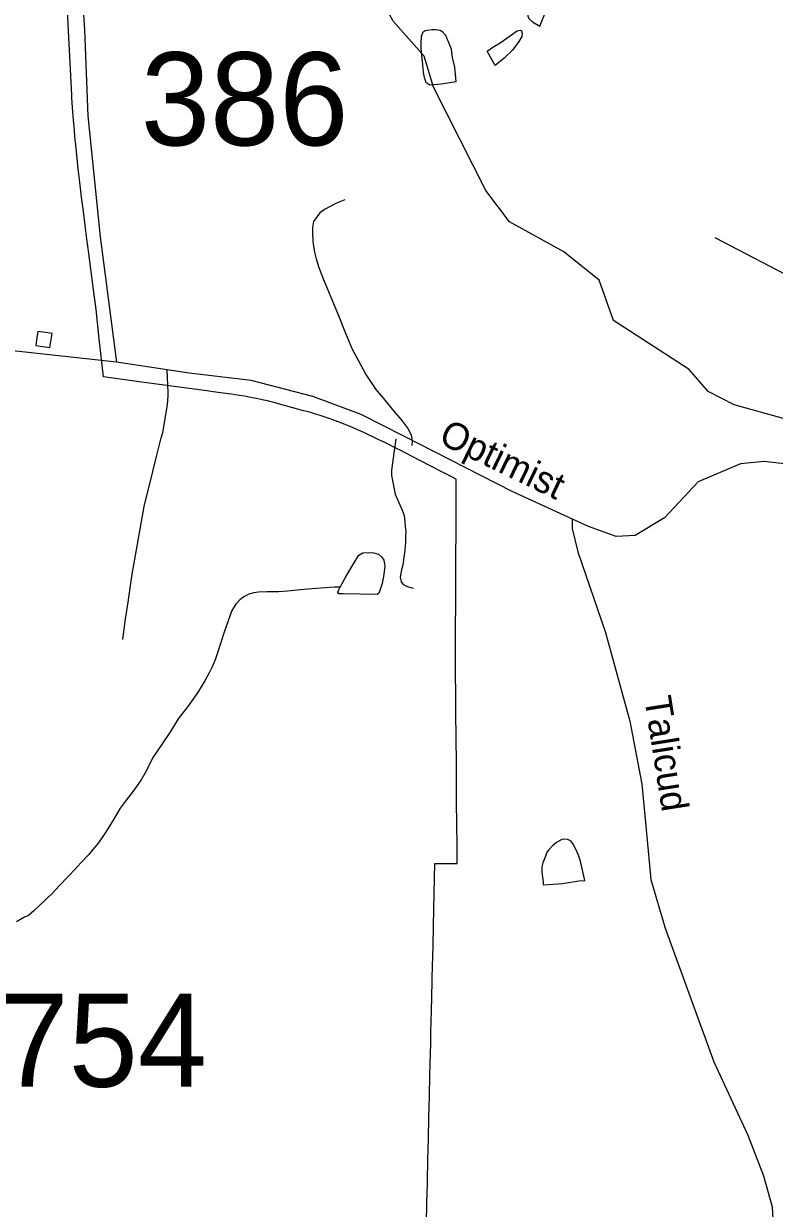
# Model space of a CAD drawing. Extents: x 2001466 to 2224147, y 644118 to 847247.
# Drawn here: x 2065640 to 2068288, y 693465 to 697641 of the extents above; entities that cross this region are included whole.
import ezdxf

# ---------------------------------------------------------------- set-up
doc = ezdxf.new("R2010")
doc.units = 0
for name, color, linetype in [('Exist Boundary Political City Limit New', 7, 'Continuous'), ('Exist Boundary Political City Limit New Hole', 7, 'Continuous'), ('Exist Hydrographic Creek Single Shore', 7, 'Continuous'), ('Exist Hydrographic Misc Water Feature', 7, 'Continuous'), ('Exist Road Non-System Type 51', 7, 'Continuous'), ('Exist Road Non-System Type 51 Label', 7, 'Continuous'), ('Exist Road Secondary Structure Standard Bridge Number Label', 7, 'Continuous'), ('Exist Road Secondary Type 51 Attributed', 7, 'Continuous'), ('Exist Road Secondary Type 51 Label', 7, 'Continuous'), ('Map Preparation Boundary City Limit Buffer Line', 7, 'Continuous')]:
    doc.layers.add(name, color=color, linetype=linetype)

msp = doc.modelspace()

# ---------------------------------------------------------------- linework, layer by layer
at = {"layer": 'Exist Boundary Political City Limit New'}
for points in [[(2066743.1, 696239.6), (2066717.6, 696248.6), (2066703, 696253.7), (2066685.5, 696259.6), (2066668.8, 696264.9), (2066652.6, 696270.1), (2066639.2, 696274.2), (2066627.4, 696276.6), (2066522.2, 696305.3), (2066508.5, 696308.9), (2066499.8, 696311), (2066481.2, 696315.1), (2066460.6, 696319.5), (2066433.6, 696324.8), (2066418.4, 696327.6), (2066400.6, 696330.6), (2066385.9, 696333), (2066372.5, 696335), (2066360.6, 696336.6), (2066300.4, 696344.8), (2066285.4, 696346.8), (2066047.5, 696378.9), (2065921.6, 696395.8), (2065906, 696529.4), (2065895.1, 696632.9), (2065885, 696712.1), (2065869.9, 696830.8), (2065863.1, 696882.2), (2065856.9, 696929.8), (2065851.8, 696970.2), (2065844.2, 697029.2), (2065838, 697081.8), (2065832.4, 697128.8), (2065827, 697178.6), (2065822.4, 697224.6), (2065821.9, 697228.9), (2065817.5, 697279.1), (2065815.6, 697301), (2065813.2, 697329.5), (2065810, 697380), (2065809.6, 697388.8), (2065803.9, 697503.7), (2065799.4, 697591.6), (2065789.8, 697783.5)], [(2067060.2, 693410.2), (2067062.1, 693485.2), (2067063.8, 693551.3), (2067063.9, 693560.1), (2067065.8, 693635.1), (2067067.6, 693710.1), (2067069.4, 693785.1), (2067071.2, 693860.1), (2067073, 693935), (2067074.8, 694010), (2067075.6, 694046.9), (2067076.6, 694085), (2067078.4, 694159.9), (2067080.9, 694264), (2067081.1, 694279.1), (2067083.9, 694391.8), (2067086.9, 694522.1), (2067090.6, 694680.9), (2067169, 694680.2), (2067168.6, 694730.8), (2067167.8, 694831.8), (2067167.2, 694884.3), (2067166.9, 694935.4), (2067166.1, 695031.3), (2067165.2, 695127.5), (2067164.6, 695207.5), (2067164.2, 695265.6), (2067163.9, 695282.5), (2067163.1, 695345.6), (2067163.5, 695433.4), (2067163.6, 695513.5), (2067164, 695593.4), (2067164, 695609.9), (2067164.2, 695673.4), (2067164.5, 695753.4), (2067164.9, 695861.2), (2067165.2, 695991.3), (2067165.4, 696035), (2067138.6, 696049), (2067116.9, 696060.5), (2067076.2, 696081.6), (2067010.1, 696115.6), (2066967.6, 696137.1), (2066962.4, 696139.8), (2066914.1, 696164.2), (2066890.8, 696175.2), (2066839.2, 696199.7), (2066791.1, 696220.6), (2066746.9, 696238.2), (2066744.4, 696239.1), (2066743.1, 696239.6)]]:
    msp.add_lwpolyline(points, dxfattribs=at)
at = {"layer": 'Exist Boundary Political City Limit New Hole'}
msp.add_lwpolyline([(2065708.1, 696553.4), (2065690.2, 696555.8), (2065685.6, 696526.8), (2065682.4, 696506.4), (2065732, 696499.9), (2065735.4, 696521.1), (2065739.9, 696549.3), (2065708.1, 696553.4)], dxfattribs=at)
at = {"layer": 'Exist Hydrographic Creek Single Shore'}
msp.add_lwpolyline([(2068324, 696247.4), (2068146.1, 696296.7), (2068054, 696344.5), (2067987.2, 696421.3), (2067720, 696594.1), (2067670.2, 696736.2), (2067545.1, 696837.2), (2067353.1, 696942.8), (2067270.1, 697052.7), (2067085.1, 697417.4), (2067052.1, 697526.3), (2066943, 697649.9), (2066592.2, 698293.6), (2066534.2, 698432.6), (2066543.9, 698555.3)], dxfattribs=at)
at = {"layer": 'Exist Hydrographic Misc Water Feature'}
for points in [[(2067452.4, 697728), (2067426.6, 697687.7), (2067418.4, 697671.9), (2067418.2, 697665.8), (2067422.5, 697657.9), (2067434.8, 697647.9), (2067460.6, 697631.8), (2067480.3, 697681.9), (2067494.4, 697720), (2067498.5, 697742.1), (2067502.2, 697759.7), (2067502.2, 697778), (2067498.5, 697785.8), (2067494.2, 697787.7), (2067484, 697788), (2067480.3, 697783.7), (2067470, 697765.8), (2067466.1, 697749.8), (2067460.4, 697737.7), (2067452.4, 697728)], [(2067056.4, 697615.2), (2067052.3, 697613), (2067046.6, 697609), (2067042.5, 697595), (2067040.4, 697575), (2067040.6, 697555.1), (2067042.7, 697529.3), (2067046.6, 697497), (2067048.9, 697469.1), (2067053, 697451), (2067058.9, 697435.1), (2067072.8, 697425.3), (2067100.9, 697427.1), (2067112.6, 697429.4)], [(2067112.6, 697429.4), (2067164.9, 697437.3), (2067160.6, 697487.4), (2067152.6, 697521.5), (2067148.7, 697551.3), (2067140.5, 697571.2), (2067128.6, 697599.3), (2067118.8, 697611), (2067108.7, 697617.4), (2067092.5, 697619.1), (2067080.6, 697619.2), (2067062.8, 697617.1), (2067056.4, 697615.2)], [(2067360.7, 697601.5), (2067380.4, 697615.5), (2067390.7, 697617.6), (2067396.2, 697616), (2067398.3, 697607.9), (2067396.6, 697595.6), (2067386.6, 697577.7), (2067364.4, 697547.8), (2067334.7, 697519.5), (2067302.7, 697493.5), (2067275, 697543.5), (2067294.7, 697557.6), (2067320.3, 697573.6), (2067332.8, 697581.8), (2067360.7, 697601.5)], [(2066756.2, 695654.9), (2066774.3, 695687.1), (2066810.2, 695749), (2066822.1, 695767), (2066836, 695775), (2066859.8, 695777.1), (2066873.9, 695775), (2066892, 695771), (2066902.2, 695761), (2066910, 695749.3), (2066914.3, 695729.1), (2066910.2, 695699.3), (2066904.1, 695667.4), (2066896.1, 695643), (2066892.4, 695633.1), (2066886.2, 695629.1), (2066766.3, 695631.1), (2066752.1, 695630.8), (2066748, 695637.1), (2066754.2, 695650.8), (2066756.2, 695654.9)], [(2066756.2, 695654.9), (2066736.1, 695654.7), (2066688.4, 695651), (2066628.1, 695646.8), (2066570.1, 695640.5), (2066538.3, 695638.5), (2066498.3, 695638.4), (2066468.3, 695636.5), (2066452.1, 695634.5), (2066434.1, 695630.3), (2066416.3, 695620.5), (2066402.7, 695610.3), (2066388.6, 695594.2), (2066374.2, 695572.1), (2066360.7, 695536), (2066346.8, 695496.3), (2066334.4, 695456), (2066324.8, 695426.2), (2066314.8, 695398.2), (2066304.7, 695374.2), (2066294.7, 695352.1), (2066278.9, 695324.1), (2066253.2, 695282.1), (2066219.4, 695234.2), (2066185.2, 695189.9), (2066157.5, 695145.8), (2066123.7, 695095.8), (2066095.8, 695053.8), (2066071.6, 695005.9), (2066053.9, 694975.7), (2066031.6, 694943.8), (2066019.5, 694925.8), (2066009.9, 694913.8), (2065997.8, 694899.5), (2065979.7, 694875.8), (2065955.7, 694833.6), (2065928, 694789.6), (2065904.3, 694753.4), (2065884, 694729.7), (2065868.2, 694711.4), (2065841.9, 694683.3), (2065820.4, 694659.5), (2065798.2, 694635.3), (2065764.4, 694601.4), (2065742.7, 694577.1), (2065720.7, 694555.3), (2065694.5, 694531.3), (2065676.2, 694513.4), (2065656.5, 694497.3), (2065642.8, 694490.9), (2065614.5, 694474.9)], [(2067540.2, 694610.5), (2067598, 694618.8), (2067619.9, 694620.7), (2067604.1, 694688.8), (2067597.8, 694706.8), (2067589.6, 694726.7), (2067577.7, 694748.8), (2067571.5, 694758.6), (2067559.8, 694764.5), (2067547.9, 694766.7), (2067537.7, 694764.6), (2067519.9, 694754.7), (2067505.5, 694742.7), (2067491.8, 694728.6), (2067485.8, 694720.6), (2067480.1, 694706.4), (2067471.7, 694682.5), (2067468.2, 694668.5), (2067468.2, 694650.6), (2067470.2, 694632.4), (2067471.9, 694614.3), (2067472.3, 694608.6), (2067474.1, 694604.7), (2067540.2, 694610.5)]]:
    msp.add_lwpolyline(points, dxfattribs=at)
at = {"layer": 'Exist Road Non-System Type 51'}
msp.add_line((2068420.2, 696708.2), (2068079.2, 696886.3), dxfattribs=at)
for points in [[(2066773.2, 697019.8), (2066743, 697008.4), (2066700.5, 696985.3), (2066684.3, 696973.6), (2066661.7, 696944.1), (2066659.2, 696922.1), (2066658.9, 696906.1), (2066660.2, 696872.1), (2066661.9, 696858), (2066665.5, 696836), (2066671, 696811.9), (2066680.4, 696781.7), (2066699.4, 696733.3), (2066750.9, 696612.2), (2066775.6, 696549.7), (2066798.5, 696493.3), (2066819.7, 696454.8), (2066846.7, 696404.3), (2066881.6, 696351.6), (2066914.8, 696312.9), (2066944.1, 696276.3), (2066973.4, 696241.7), (2066994.8, 696213.3), (2067006.3, 696191), (2067009.9, 696170.9), (2067009, 696153.4)], [(2065989.7, 695470.6), (2065994.4, 695506.5), (2065999.2, 695542.4), (2066008.4, 695602.2), (2066022.4, 695699.9), (2066033.7, 695765.7), (2066065.3, 695939), (2066095.8, 696062.4), (2066109, 696120.1), (2066124.1, 696175.8), (2066130.6, 696199.7), (2066146.6, 696297.4), (2066149.2, 696329.3), (2066149.5, 696341.3), (2066146.5, 696420.3)], [(2066952.8, 696177.3), (2066937.8, 696066.4), (2066937.4, 696048.4), (2066950.1, 695982.2), (2066974.9, 695925.7), (2066982.5, 695907.5), (2066984.1, 695885.5), (2066985.7, 695867.4), (2066987.4, 695853.4), (2066987, 695833.4), (2066986.6, 695813.4), (2066984, 695785.5), (2066977, 695733.6), (2066972.6, 695715.7), (2066968.1, 695689.8), (2066971.8, 695673.7), (2066977.6, 695665.6), (2066987.5, 695659.4), (2066997.4, 695655.2), (2067013.3, 695650.9)], [(2067575, 695894.6), (2067575, 695861.1), (2067594.5, 695779.2), (2067691.9, 695494.4), (2067777.7, 695182.3), (2067820.6, 694959.9), (2067836.2, 694800), (2067851.8, 694624.4), (2067902.4, 694452.8), (2068074, 693980.7), (2068194.8, 693723.3), (2068249.4, 693578.9), (2068280.6, 693469.7), (2068284.5, 693383.8), (2068280.6, 693020.3), (2068268.9, 692914.9), (2068218.2, 692813.5), (2068187, 692692.6), (2068136.4, 692645.7)]]:
    msp.add_lwpolyline(points, dxfattribs=at)
at = {"layer": 'Exist Road Secondary Type 51 Attributed'}
for points in [[(2065834.2, 697928.3), (2065854, 697618.8), (2065865.8, 697315.6), (2065910, 696889.2), (2065966.7, 696447.9)], [(2065966.7, 696447.9), (2065580.1, 696490.5), (2065197.5, 696517.4), (2064710.7, 696544.2), (2064376.1, 696564.8), (2064125.2, 696582.1), (2063997.4, 696577.4), (2063635.3, 696511.1), (2063370.2, 696457.4), (2063105.1, 696380)], [(2068425.2, 696078), (2068252.2, 696097.1), (2068168.6, 696089), (2068019.7, 696026.3), (2067899.8, 695898.4), (2067797.2, 695836.8), (2067730.1, 695833.6), (2067632.3, 695868.4), (2067363.2, 695991.5), (2066981.4, 696187.4), (2066829.9, 696263.1), (2066659.5, 696326.3), (2066441.7, 696383.2), (2066223.9, 696408.4), (2065966.7, 696447.9)]]:
    msp.add_lwpolyline(points, dxfattribs=at)
at = {"layer": 'Map Preparation Boundary City Limit Buffer Line'}
for points in [[(2066743.1, 696239.6), (2066717.6, 696248.6), (2066703, 696253.7), (2066685.5, 696259.6), (2066668.8, 696264.9), (2066652.6, 696270.1), (2066639.2, 696274.2), (2066627.4, 696276.6), (2066522.2, 696305.3), (2066508.5, 696308.9), (2066499.8, 696311), (2066481.2, 696315.1), (2066460.6, 696319.5), (2066433.6, 696324.8), (2066418.4, 696327.6), (2066400.6, 696330.6), (2066385.9, 696333), (2066372.5, 696335), (2066360.6, 696336.6), (2066300.4, 696344.8), (2066285.4, 696346.8), (2066047.5, 696378.9), (2065921.6, 696395.8), (2065906, 696529.4), (2065895.1, 696632.9), (2065885, 696712.1), (2065869.9, 696830.8), (2065863.1, 696882.2), (2065856.9, 696929.8), (2065851.8, 696970.2), (2065844.2, 697029.2), (2065838, 697081.8), (2065832.4, 697128.8), (2065827, 697178.6), (2065822.4, 697224.6), (2065821.9, 697228.9), (2065817.5, 697279.1), (2065815.6, 697301), (2065813.2, 697329.5), (2065810, 697380), (2065809.6, 697388.8), (2065803.9, 697503.7), (2065799.4, 697591.6), (2065789.8, 697783.5)], [(2065708.1, 696553.4), (2065690.2, 696555.8), (2065685.6, 696526.8), (2065682.4, 696506.4), (2065732, 696499.9), (2065735.4, 696521.1), (2065739.9, 696549.3), (2065708.1, 696553.4)], [(2067060.2, 693410.2), (2067062.1, 693485.2), (2067063.8, 693551.3), (2067063.9, 693560.1), (2067065.8, 693635.1), (2067067.6, 693710.1), (2067069.4, 693785.1), (2067071.2, 693860.1), (2067073, 693935), (2067074.8, 694010), (2067075.6, 694046.9), (2067076.6, 694085), (2067078.4, 694159.9), (2067080.9, 694264), (2067081.1, 694279.1), (2067083.9, 694391.8), (2067086.9, 694522.1), (2067090.6, 694680.9), (2067169, 694680.2), (2067168.6, 694730.8), (2067167.8, 694831.8), (2067167.2, 694884.3), (2067166.9, 694935.4), (2067166.1, 695031.3), (2067165.2, 695127.5), (2067164.6, 695207.5), (2067164.2, 695265.6), (2067163.9, 695282.5), (2067163.1, 695345.6), (2067163.5, 695433.4), (2067163.6, 695513.5), (2067164, 695593.4), (2067164, 695609.9), (2067164.2, 695673.4), (2067164.5, 695753.4), (2067164.9, 695861.2), (2067165.2, 695991.3), (2067165.4, 696035), (2067138.6, 696049), (2067116.9, 696060.5), (2067076.2, 696081.6), (2067010.1, 696115.6), (2066967.6, 696137.1), (2066962.4, 696139.8), (2066914.1, 696164.2), (2066890.8, 696175.2), (2066839.2, 696199.7), (2066791.1, 696220.6), (2066746.9, 696238.2), (2066744.4, 696239.1), (2066743.1, 696239.6)]]:
    msp.add_lwpolyline(points, dxfattribs=at)

# ---------------------------------------------------------------- texts
at = {"layer": 'Exist Road Non-System Type 51 Label'}
msp.add_text('Talicud', height=95, rotation=278.9537, dxfattribs=at).set_placement((2067828.6, 695263.3))
at = {"layer": 'Exist Road Secondary Structure Standard Bridge Number Label'}
for s, p in [('386', (2066053.2, 697211.9)), ('754', (2065554.4, 693893.3))]:
    msp.add_text(s, height=328.08, dxfattribs=at).set_placement(p)
at = {"layer": 'Exist Road Secondary Type 51 Label'}
msp.add_text('Optimist', height=95, rotation=334.1991, dxfattribs=at).set_placement((2067099.4, 696164.3))

doc.saveas('drawing.dxf')
